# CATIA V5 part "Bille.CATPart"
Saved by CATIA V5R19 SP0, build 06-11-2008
Part number: Bille
Publications: "Rayon_bille"
Bounding box of the stored display mesh (mm): x -9.942 to 9.942, y -10 to 10, z -9.942 to 9.942
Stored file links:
  F:\! CONCEPTION\PROJET\Mécanisme 11\CAO\Bille.CATPart
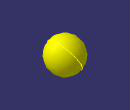
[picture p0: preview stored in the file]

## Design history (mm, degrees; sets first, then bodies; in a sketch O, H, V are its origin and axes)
Parameters
  Rayon_bille = 10 mm
Body1 (main body)
  Sketch1 on yz-plane, origin (0, 0, 0), H (0, 1, 0), V (0, 0, 1)
    arc A1 centre (0, 0) radius 10 from (10, 0) to (-10, 0) ccw
    point P1 (0, 0)
    point P2 (10, 0)
    line L1 (-10, 0) -> (10, 0)
    radius A1 = 10 {= Rayon_bille}
    coincidence: P1 H, P2 H, P1 O
    horizontal: L1 H
  Shaft1: profile Sketch1, axis Sketch1.H, angle 360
